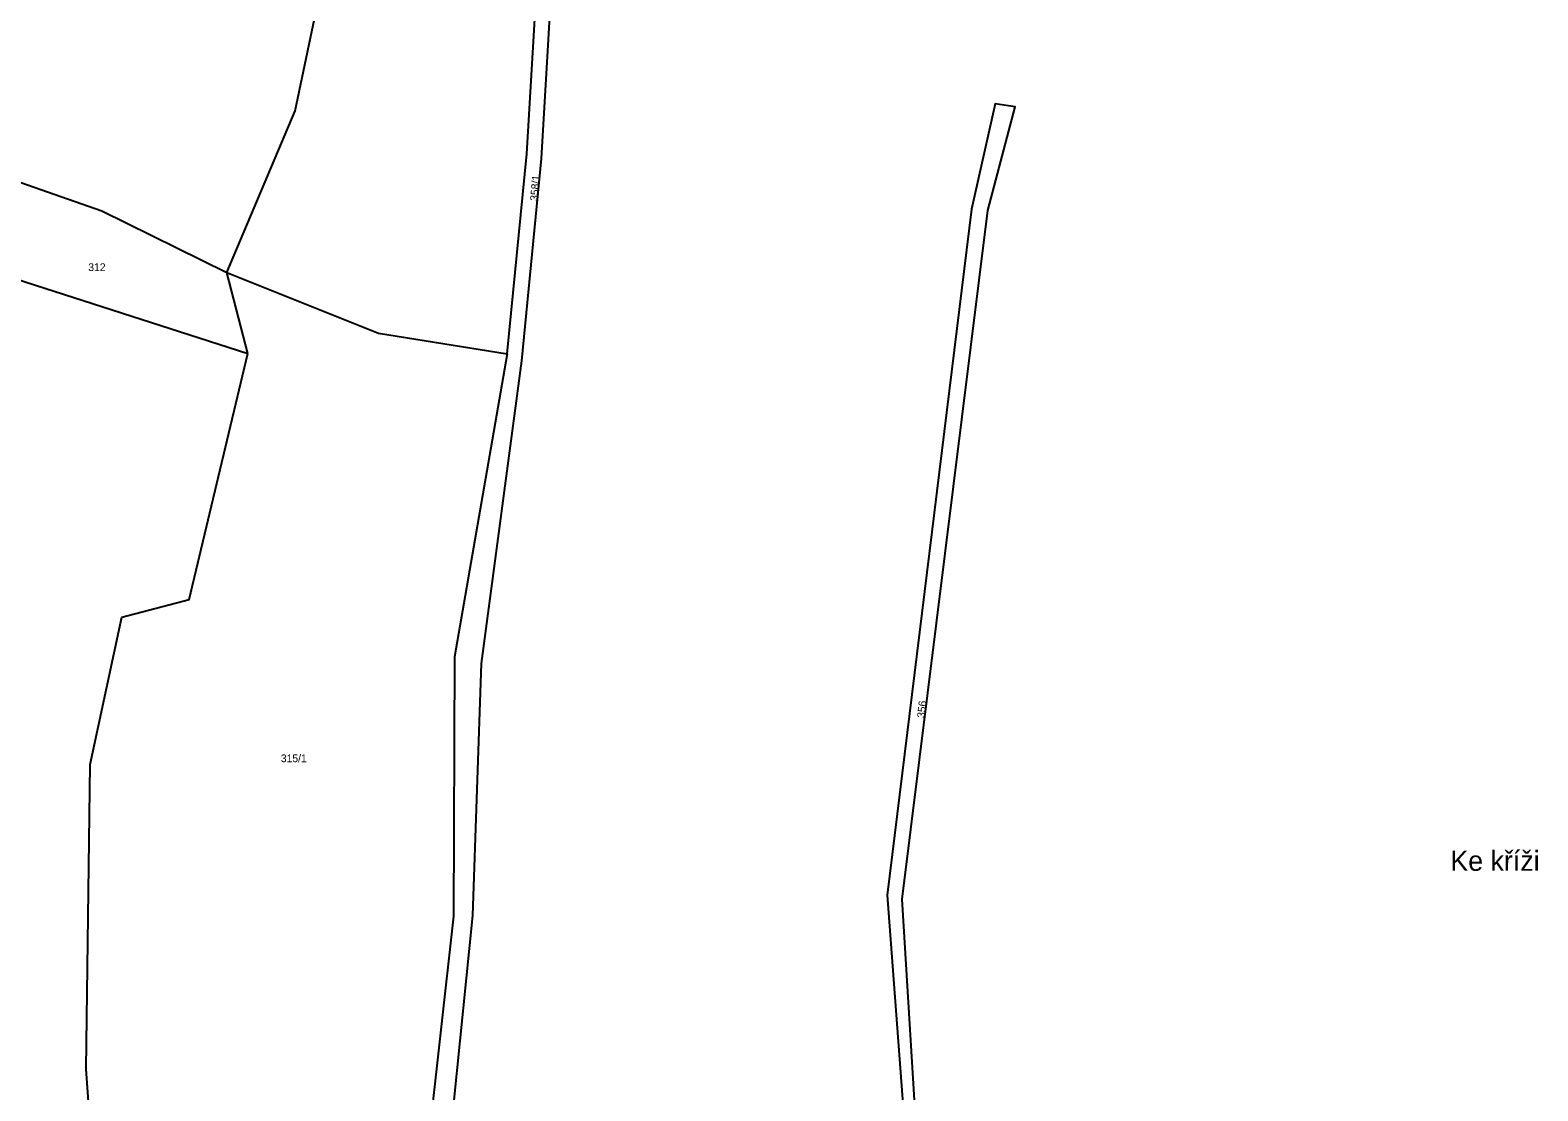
# Model space of a CAD drawing. Extents: x -880531 to -877616, y -1023932 to -1021350.
# Drawn here: x -878781.4 to -878450.2, y -1022197 to -1021964.1 of the extents above; entities that cross this region are included whole.
import ezdxf

# ---------------------------------------------------------------- set-up
doc = ezdxf.new("R2010")
doc.units = 0
for name, color, linetype in [('Hranice parcel', 7, 'Continuous'), ('Parcelní čísla', 7, 'Continuous'), ('Pop  PČ popisy', 7, 'Continuous')]:
    doc.layers.add(name, color=color, linetype=linetype)

msp = doc.modelspace()

# ---------------------------------------------------------------- linework, layer by layer
at = {"layer": 'Hranice parcel'}
for p, q in [((-878796.62, -1022014.79), (-878733.6, -1022035.04)), ((-878733.6, -1022035.04), (-878738.23, -1022017.29))]:
    msp.add_line(p, q, dxfattribs=at)
for points in [[(-878693.21, -1022298.36), (-878692.4, -1022258.3), (-878689.78, -1022213.59), (-878684.22, -1022158.54), (-878682.26, -1022103.14), (-878673.47, -1022036.72), (-878669.09, -1021992.24), (-878665.96, -1021938.56), (-878659.56, -1021864.21), (-878651.12, -1021830.64), (-878647.4, -1021802.19), (-878644.62, -1021778.59), (-878640.81, -1021757.55), (-878636.77, -1021734.3), (-878635.51, -1021701.34), (-878633.33, -1021667.69), (-878631.59, -1021625.86), (-878630.9, -1021607.55), (-878630.94, -1021582.96), (-878627.58, -1021573.01)], [(-878738.23, -1022017.29), (-878723.26, -1021981.78), (-878714.09, -1021938.14), (-878707.13, -1021902.81), (-878706.39, -1021894.96), (-878699.38, -1021870.84), (-878691.7, -1021843.88), (-878684.82, -1021819.64), (-878653.45, -1021825.8)], [(-878676.69, -1022035.16), (-878672.32, -1021991.2), (-878669.14, -1021936.84), (-878663.28, -1021863.62), (-878653.45, -1021825.8)], [(-878586.62, -1022208.6), (-878589.91, -1022154.89), (-878571.07, -1022003.66), (-878565.03, -1021980.86), (-878569.45, -1021980.25), (-878574.67, -1022003.38), (-878593.2, -1022154.07), (-878589.06, -1022208.62)], [(-878795.54, -1021993.32), (-878765.72, -1022003.77), (-878738.23, -1022017.29)], [(-878738.23, -1022017.29), (-878704.91, -1022030.64), (-878676.69, -1022035.16)], [(-878768.4, -1022202.48), (-878769.12, -1022192.22), (-878768.28, -1022125.33), (-878761.32, -1022093.01), (-878746.55, -1022089.12), (-878733.6, -1022035.04)], [(-878676.69, -1022035.16), (-878688.26, -1022101.67), (-878688.42, -1022158.68), (-878694.18, -1022209.89)]]:
    msp.add_lwpolyline(points, dxfattribs=at)

# ---------------------------------------------------------------- texts
at = {"layer": 'Parcelní čísla'}
for s, rotation, p in [('358/1', 85, (-878669.943, -1022001.624)), ('356', 84, (-878584.924, -1022115.188))]:
    msp.add_text(s, height=1.7, rotation=rotation, dxfattribs=at).set_placement(p)
for s, p in [('312', (-878768.68, -1022016.97)), ('315/1', (-878726.38, -1022124.84))]:
    msp.add_text(s, height=1.7, dxfattribs=at).set_placement(p)
at = {"layer": 'Pop  PČ popisy'}
msp.add_text('Ke kříži', height=4.4, dxfattribs=at).set_placement((-878469.45, -1022148.7))

doc.saveas('drawing.dxf')
